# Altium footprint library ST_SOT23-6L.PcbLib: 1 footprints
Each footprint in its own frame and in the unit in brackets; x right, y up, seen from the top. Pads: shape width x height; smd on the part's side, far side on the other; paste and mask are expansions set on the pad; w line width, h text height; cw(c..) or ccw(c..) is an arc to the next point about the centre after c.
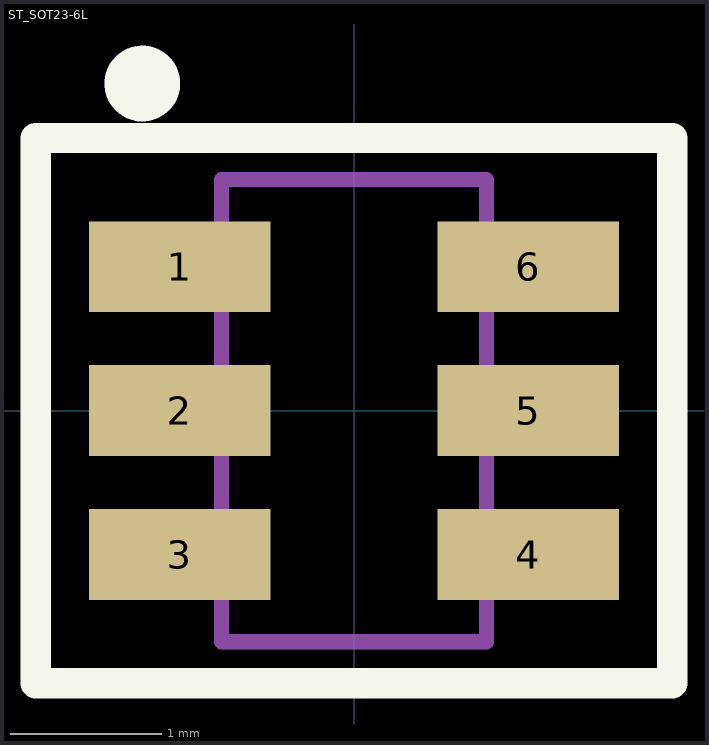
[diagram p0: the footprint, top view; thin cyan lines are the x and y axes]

## ST_SOT23-6L [mm] "SOT23, 6-Leads, Body 2.93x2.80mm, Pitch 0.95mm, IPC Medium Density"
height 1.45
pads (6):
  rect 1.2x0.6 smd: 1(-1.15,0.95) 2(-1.15,0) 3(-1.15,-0.95) 4(1.15,-0.95) 5(1.15,0) 6(1.15,0.95)
Top Overlay:
  circle w0.25: c-1.397,2.159 r0.125
  lines w0.2: -2.1,-1.8 2.1,-1.8 2.1,1.8 -2.1,1.8 -2.1,-1.8
Mechanical 13:
  lines w0.1: -0.875,-1.525 -0.875,1.525 0.875,1.525 0.875,-1.525 -0.875,-1.525
3D body "ST_SOT23-6L.step": height 1.45, standoff 0, extent -1.6,-1.525 1.6,1.525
